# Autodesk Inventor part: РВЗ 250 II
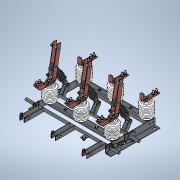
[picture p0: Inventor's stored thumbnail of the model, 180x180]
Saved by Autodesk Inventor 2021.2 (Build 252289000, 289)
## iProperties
Created: 1900-01
Part Number: РВЗ 250 II
Material: Типовые
Description: STEP AP242
Document SubType Name: Modeling
Designer: pc
Density: 1 g/cm^3
Appearance: По умолчанию
Company: UNSPECIFIED
Title: ÐÂÇ 250 II
Author: UNSPECIFIED
Revision Number: ANYUNSPECIFIED
Sending System: C3D Toolkit
Preprocessor: C3D Converter
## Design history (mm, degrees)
feature "БазТело1"
feature "БазТело2"
feature "БазТело3"
feature "БазТело4"
feature "БазТело5"
feature "БазТело6"
feature "БазТело7"
feature "БазТело8"
feature "БазТело9"
feature "БазТело10"
feature "БазТело11"
feature "Составной1"
node "Твердое тело1"
node "Твердое тело2"
node "Твердое тело3"
node "Твердое тело4"
node "Твердое тело5"
node "Твердое тело6"
node "Твердое тело7"
node "Твердое тело8"
node "Твердое тело9"
node "Твердое тело10"
node "Твердое тело11"
body "SRF1"
